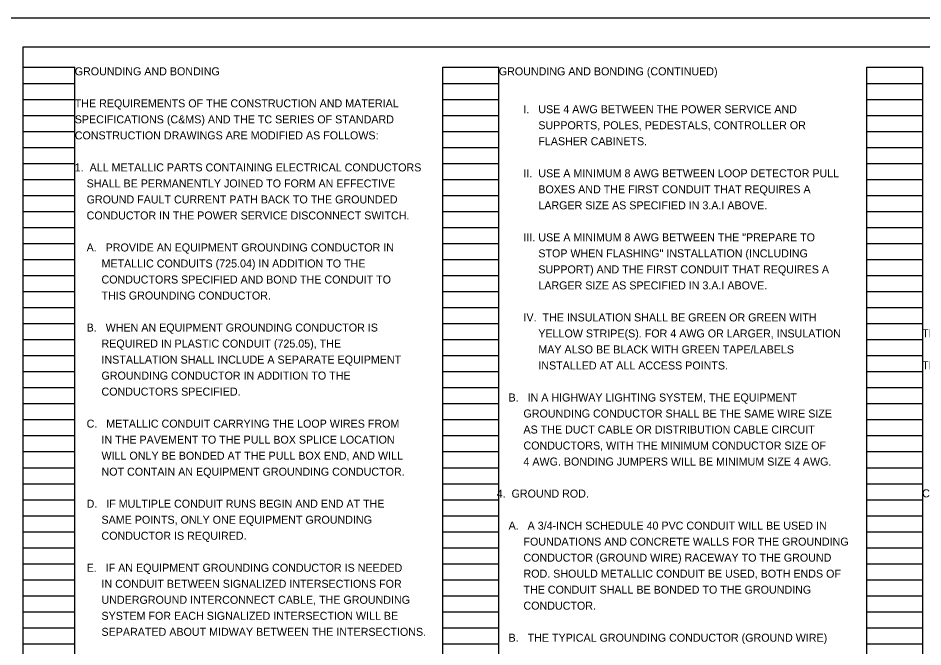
# Model space of a CAD drawing. Extents: x -18.7 to 62.3, y -3.1 to 33.6.
# Drawn here: x 1.91 to 17.74, y 11.01 to 22 of the extents above; entities that cross this region are included whole.
import ezdxf

# ---------------------------------------------------------------- set-up
doc = ezdxf.new("R2010")
doc.units = 0
for name, color, linetype in [('SH_Border', 7, 'Continuous'), ('SH_Cut_Line', 7, 'Continuous'), ('SH_Data', 7, 'Continuous'), ('SH_Text', 7, 'Continuous')]:
    doc.layers.add(name, color=color, linetype=linetype)

msp = doc.modelspace()

# ---------------------------------------------------------------- linework, layer by layer
at = {"layer": 'SH_Border'}
msp.add_lwpolyline([(2.001, 21.5), (33.501, 21.5), (33.501, 0.5), (2.001, 0.5)], close=True, dxfattribs=at)
at = {"layer": 'SH_Cut_Line'}
msp.add_lwpolyline([(0.001, 0), (34.001, 0), (34.001, 22), (0.001, 22)], close=True, dxfattribs=at)
at = {"layer": 'SH_Data'}
for p, q in [((2.001, 0.98), (2.001, 21.14)), ((2.001, 21.14), (2.901, 21.14)), ((2.901, 0.98), (2.901, 21.14)), ((9.341, 0.98), (9.341, 21.14)), ((9.341, 21.14), (10.321, 21.14)), ((10.321, 0.98), (10.321, 21.14)), ((16.761, 0.98), (16.761, 21.14)), ((16.761, 21.14), (17.741, 21.14)), ((17.741, 0.98), (17.741, 21.14)), ((2.001, 20.86), (2.901, 20.86)), ((9.341, 20.86), (10.321, 20.86)), ((16.761, 20.86), (17.741, 20.86)), ((2.001, 20.58), (2.901, 20.58)), ((9.341, 20.58), (10.321, 20.58)), ((16.761, 20.58), (17.741, 20.58)), ((2.001, 20.3), (2.901, 20.3)), ((9.341, 20.3), (10.321, 20.3)), ((16.761, 20.3), (17.741, 20.3)), ((2.001, 20.02), (2.901, 20.02)), ((9.341, 20.02), (10.321, 20.02)), ((16.761, 20.02), (17.741, 20.02)), ((2.001, 19.74), (2.901, 19.74)), ((9.341, 19.74), (10.321, 19.74)), ((16.761, 19.74), (17.741, 19.74)), ((2.001, 19.46), (2.901, 19.46)), ((9.341, 19.46), (10.321, 19.46)), ((16.761, 19.46), (17.741, 19.46)), ((2.001, 19.18), (2.901, 19.18)), ((9.341, 19.18), (10.321, 19.18)), ((16.761, 19.18), (17.741, 19.18)), ((2.001, 18.9), (2.901, 18.9)), ((9.341, 18.9), (10.321, 18.9)), ((16.761, 18.9), (17.741, 18.9)), ((2.001, 18.62), (2.901, 18.62)), ((9.341, 18.62), (10.321, 18.62)), ((16.761, 18.62), (17.741, 18.62)), ((2.001, 18.34), (2.901, 18.34)), ((9.341, 18.34), (10.321, 18.34)), ((16.761, 18.34), (17.741, 18.34)), ((2.001, 18.06), (2.901, 18.06)), ((9.341, 18.06), (10.321, 18.06)), ((16.761, 18.06), (17.741, 18.06)), ((2.001, 17.78), (2.901, 17.78)), ((9.341, 17.78), (10.321, 17.78)), ((16.761, 17.78), (17.741, 17.78)), ((2.001, 17.5), (2.901, 17.5)), ((9.341, 17.5), (10.321, 17.5)), ((16.761, 17.5), (17.741, 17.5)), ((2.001, 17.22), (2.901, 17.22)), ((9.341, 17.22), (10.321, 17.22)), ((16.761, 17.22), (17.741, 17.22)), ((2.001, 16.94), (2.901, 16.94)), ((9.341, 16.94), (10.321, 16.94)), ((16.761, 16.94), (17.741, 16.94)), ((2.001, 16.66), (2.901, 16.66)), ((9.341, 16.66), (10.321, 16.66)), ((16.761, 16.66), (17.741, 16.66)), ((2.001, 16.38), (2.901, 16.38)), ((9.341, 16.38), (10.321, 16.38)), ((16.761, 16.38), (17.741, 16.38)), ((2.001, 16.1), (2.901, 16.1)), ((9.341, 16.1), (10.321, 16.1)), ((16.761, 16.1), (17.741, 16.1)), ((2.001, 15.82), (2.901, 15.82)), ((9.341, 15.82), (10.321, 15.82)), ((16.761, 15.82), (17.741, 15.82)), ((2.001, 15.54), (2.901, 15.54)), ((9.341, 15.54), (10.321, 15.54)), ((16.761, 15.54), (17.741, 15.54)), ((2.001, 15.26), (2.901, 15.26)), ((9.341, 15.26), (10.321, 15.26)), ((16.761, 15.26), (17.741, 15.26)), ((2.001, 14.98), (2.901, 14.98)), ((9.341, 14.98), (10.321, 14.98)), ((16.761, 14.98), (17.741, 14.98)), ((2.001, 14.7), (2.901, 14.7)), ((9.341, 14.7), (10.321, 14.7)), ((16.761, 14.7), (17.741, 14.7)), ((2.001, 14.42), (2.901, 14.42)), ((9.341, 14.42), (10.321, 14.42)), ((16.761, 14.42), (17.741, 14.42)), ((2.001, 14.14), (2.901, 14.14)), ((9.341, 14.14), (10.321, 14.14)), ((16.761, 14.14), (17.741, 14.14)), ((2.001, 13.86), (2.901, 13.86)), ((9.341, 13.86), (10.321, 13.86)), ((16.761, 13.86), (17.741, 13.86)), ((2.001, 13.58), (2.901, 13.58)), ((9.341, 13.58), (10.321, 13.58)), ((16.761, 13.58), (17.741, 13.58)), ((2.001, 13.3), (2.901, 13.3)), ((9.341, 13.3), (10.321, 13.3)), ((16.761, 13.3), (17.741, 13.3)), ((2.001, 13.02), (2.901, 13.02)), ((9.341, 13.02), (10.321, 13.02)), ((16.761, 13.02), (17.741, 13.02)), ((2.001, 12.74), (2.901, 12.74)), ((9.341, 12.74), (10.321, 12.74)), ((16.761, 12.74), (17.741, 12.74)), ((2.001, 12.46), (2.901, 12.46)), ((9.341, 12.46), (10.321, 12.46)), ((16.761, 12.46), (17.741, 12.46)), ((2.001, 12.18), (2.901, 12.18)), ((9.341, 12.18), (10.321, 12.18)), ((16.761, 12.18), (17.741, 12.18)), ((2.001, 11.9), (2.901, 11.9)), ((9.341, 11.9), (10.321, 11.9)), ((16.761, 11.9), (17.741, 11.9)), ((2.001, 11.62), (2.901, 11.62)), ((9.341, 11.62), (10.321, 11.62)), ((16.761, 11.62), (17.741, 11.62)), ((2.001, 11.34), (2.901, 11.34)), ((9.341, 11.34), (10.321, 11.34)), ((16.761, 11.34), (17.741, 11.34)), ((2.001, 11.06), (2.901, 11.06)), ((9.341, 11.06), (10.321, 11.06)), ((16.761, 11.06), (17.741, 11.06))]:
    msp.add_line(p, q, dxfattribs=at)

# ---------------------------------------------------------------- texts
at = {"layer": 'SH_Text'}
for s, p in [('GROUNDING AND BONDING', (2.901, 21)), ('GROUNDING AND BONDING (CONTINUED)', (10.321, 21)), ('THE REQUIREMENTS OF THE CONSTRUCTION AND MATERIAL', (2.901, 20.44)), ('         I.   USE 4 AWG BETWEEN THE POWER SERVICE AND', (10.284, 20.337)), ('SPECIFICATIONS (C&MS) AND THE TC SERIES OF STANDARD', (2.901, 20.16)), ('              SUPPORTS, POLES, PEDESTALS, CONTROLLER OR', (10.284, 20.057)), ('CONSTRUCTION DRAWINGS ARE MODIFIED AS FOLLOWS:', (2.901, 19.88)), ('              FLASHER CABINETS.', (10.284, 19.777)), ('1.  ALL METALLIC PARTS CONTAINING ELECTRICAL CONDUCTORS', (2.901, 19.32)), ('         II.  USE A MINIMUM 8 AWG BETWEEN LOOP DETECTOR PULL', (10.284, 19.217)), ('    SHALL BE PERMANENTLY JOINED TO FORM AN EFFECTIVE', (2.901, 19.04)), ('              BOXES AND THE FIRST CONDUIT THAT REQUIRES A', (10.284, 18.937)), ('    GROUND FAULT CURRENT PATH BACK TO THE GROUNDED', (2.901, 18.76)), ('              LARGER SIZE AS SPECIFIED IN 3.A.I ABOVE.', (10.284, 18.657)), ('    CONDUCTOR IN THE POWER SERVICE DISCONNECT SWITCH.', (2.901, 18.48)), ('         III. USE A MINIMUM 8 AWG BETWEEN THE "PREPARE TO', (10.284, 18.097)), ('    A.   PROVIDE AN EQUIPMENT GROUNDING CONDUCTOR IN', (2.901, 17.92)), ('              STOP WHEN FLASHING" INSTALLATION (INCLUDING', (10.284, 17.817)), ('         METALLIC CONDUITS (725.04) IN ADDITION TO THE', (2.901, 17.64)), ('              SUPPORT) AND THE FIRST CONDUIT THAT REQUIRES A', (10.284, 17.537)), ('         CONDUCTORS SPECIFIED AND BOND THE CONDUIT TO', (2.901, 17.36)), ('              LARGER SIZE AS SPECIFIED IN 3.A.I ABOVE.', (10.284, 17.257)), ('         THIS GROUNDING CONDUCTOR.', (2.901, 17.08)), ('         IV.  THE INSULATION SHALL BE GREEN OR GREEN WITH', (10.284, 16.697)), ('    B.   WHEN AN EQUIPMENT GROUNDING CONDUCTOR IS', (2.901, 16.52)), ('              YELLOW STRIPE(S). FOR 4 AWG OR LARGER, INSULATION', (10.284, 16.417)), ('THIS ITEM IS TO REALIGN EXISTING CONDUIT FROM AN ', (17.728, 16.421)), ('         REQUIRED IN PLASTIC CONDUIT (725.05), THE', (2.901, 16.24)), ('              MAY ALSO BE BLACK WITH GREEN TAPE/LABELS', (10.284, 16.137)), ('         INSTALLATION SHALL INCLUDE A SEPARATE EQUIPMENT', (2.901, 15.96)), ('              INSTALLED AT ALL ACCESS POINTS.', (10.284, 15.857)), ('THE PLANS TO THE PROPOSED PULL BOX. THIS', (17.728, 15.861)), ('         GROUNDING CONDUCTOR IN ADDITION TO THE', (2.901, 15.68)), ('         CONDUCTORS SPECIFIED.', (2.901, 15.4)), ('    B.   IN A HIGHWAY LIGHTING SYSTEM, THE EQUIPMENT', (10.284, 15.297)), ('         GROUNDING CONDUCTOR SHALL BE THE SAME WIRE SIZE', (10.284, 15.017)), ('    C.   METALLIC CONDUIT CARRYING THE LOOP WIRES FROM', (2.901, 14.84)), ('         AS THE DUCT CABLE OR DISTRIBUTION CABLE CIRCUIT', (10.284, 14.737)), ('         IN THE PAVEMENT TO THE PULL BOX SPLICE LOCATION', (2.901, 14.56)), ('         CONDUCTORS, WITH THE MINIMUM CONDUCTOR SIZE OF', (10.284, 14.457)), ('         WILL ONLY BE BONDED AT THE PULL BOX END, AND WILL', (2.901, 14.28)), ('         4 AWG. BONDING JUMPERS WILL BE MINIMUM SIZE 4 AWG.', (10.284, 14.177)), ('         NOT CONTAIN AN EQUIPMENT GROUNDING CONDUCTOR.', (2.901, 14)), ('4.  GROUND ROD.', (10.284, 13.617)), ('CONDUCTORS, FURNISHED AND INSTALLED, INCLUDING ALL ', (17.728, 13.621)), ('    D.   IF MULTIPLE CONDUIT RUNS BEGIN AND END AT THE', (2.901, 13.44)), ('         SAME POINTS, ONLY ONE EQUIPMENT GROUNDING', (2.901, 13.16)), ('    A.   A 3/4-INCH SCHEDULE 40 PVC CONDUIT WILL BE USED IN', (10.284, 13.057)), ('         CONDUCTOR IS REQUIRED.', (2.901, 12.88)), ('         FOUNDATIONS AND CONCRETE WALLS FOR THE GROUNDING', (10.284, 12.777)), ('         CONDUCTOR (GROUND WIRE) RACEWAY TO THE GROUND', (10.284, 12.497)), ('    E.   IF AN EQUIPMENT GROUNDING CONDUCTOR IS NEEDED', (2.901, 12.32)), ('         ROD. SHOULD METALLIC CONDUIT BE USED, BOTH ENDS OF', (10.284, 12.217)), ('         IN CONDUIT BETWEEN SIGNALIZED INTERSECTIONS FOR', (2.901, 12.04)), ('         THE CONDUIT SHALL BE BONDED TO THE GROUNDING', (10.284, 11.937)), ('         UNDERGROUND INTERCONNECT CABLE, THE GROUNDING', (2.901, 11.76)), ('         CONDUCTOR.', (10.284, 11.657)), ('         SYSTEM FOR EACH SIGNALIZED INTERSECTION WILL BE', (2.901, 11.48)), ('         SEPARATED ABOUT MIDWAY BETWEEN THE INTERSECTIONS.', (2.901, 11.2)), ('    B.   THE TYPICAL GROUNDING CONDUCTOR (GROUND WIRE)', (10.284, 11.097))]:
    msp.add_text(s, height=0.14, dxfattribs=at).set_placement(p)

doc.saveas('drawing.dxf')
